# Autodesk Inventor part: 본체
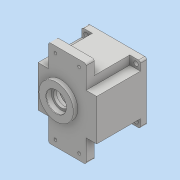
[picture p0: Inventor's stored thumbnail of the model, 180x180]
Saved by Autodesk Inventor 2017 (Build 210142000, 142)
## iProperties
Part Number: 본체
Material: 일반
Document SubType Name: Modeling
Designer: user
Density: 1 g/cm^3
Appearance: 기본값
Author: user
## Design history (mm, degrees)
sketch "스케치1"
  geometry: L1 (-30, 70)-(30, 70); L2 (30, -70)-(-30, -70); L3 (-30, 70)-(30, -70); L4 (30, 70)-(-30, -70); L5 (47, 33)-(47, -33); L6 (-47, -33)-(-47, 33); L7 (-47, 33)-(47, -33); L8 (47, 33)-(-47, -33); L9 (30, 70)-(30, 33); L10 (30, -33)-(30, -70); L11 (-47, 33)-(-30, 33); L12 (30, 33)-(47, 33); L13 (-30, -70)-(-30, -33); L14 (-30, 33)-(-30, 70); L15 (47, -33)-(30, -33); L16 (-30, -33)-(-47, -33); 1 further point
  constraints: 32 end point, 10 parallel, 4 midpoint, 4 perpendicular, 3 horizontal
  dimensions: "d6" = 60 distance of L2.start L2.end; "d7" = 140 distance of L1.end L2.start; "d8" = 94 distance of L5.end L6.start; "d9" = 66 distance of L5.start L5.end; "d10" = 60 distance of L1.start L1.end; "d11" = 66 distance of L6.start L6.end; "d12" = 37 distance of L11.end L1.start; "d13" = 37 distance of L2.end L13.end
extrude "돌출1" new body sketch "스케치1" distance "d14" = 13; taper "d15" = 0 deg
sketch "스케치2"
  geometry: L1 (-30, 33)-(-30, 70) reference; L2 (30, -33)-(47, -33) reference; L3 (47, 33)-(47, -33); L4 (-47, -33)-(-47, 33); L5 (-47, 33)-(47, -33); L6 (47, 33)-(-47, -33); L7 (30, -70)-(30, -33) reference; L8 (-30, 47)-(30, 47); L9 (30, -47)-(-30, -47); L10 (-30, 47)-(30, -47); L11 (30, 47)-(-30, -47); L12 (30, 47)-(30, 33); L13 (30, -33)-(30, -47); L14 (-47, 33)-(-30, 33); L15 (30, 33)-(47, 33); L16 (47, -33)-(30, -33); L17 (-30, -33)-(-47, -33); L18 (-30, -47)-(-30, -33); L19 (-30, 33)-(-30, 47); 1 further point
  constraints: 32 end point, 10 parallel, 4 midpoint, 4 perpendicular, 3 horizontal, 1 point on line
  dimensions: "d31" = 94 distance of L8.end L9.start; "d32" = 60 distance of L8.start L8.end; "d33" = 66 distance of L4.start L4.end; "d34" = 60 distance of L9.start L9.end; "d35" = 17 distance of L4.end L14.end
extrude "돌출2" join sketch "스케치2" distance "d16" = 57; taper "d17" = 0 deg
sketch "스케치3"
  geometry: L1 (47, -47)-(-47, -47); L2 (-47, -47)-(-47, 47); L3 (-47, 47)-(47, 47); L4 (47, 47)-(47, -47); L5 (47, -47)-(-47, 47); L6 (-47, -47)-(47, 47); 1 further point
  constraints: 12 end point, 2 midpoint, 2 parallel, 1 horizontal, 1 perpendicular
  dimensions: "d18" = 94 distance of L2.end L3.end; "d19" = 94 distance of L1.end L2.end
extrude "돌출3" join sketch "스케치3" distance "d20" = 10; taper "d21" = 0 deg
sketch "스케치4"
  geometry: C1 r 43 at (0, 0); 1 further point
  constraints: 1 centre point, 1 coincident
  dimensions: "d22" = 86 diameter of C1
extrude "돌출4" cut sketch "스케치4" distance "d23" = 9; taper "d24" = 0 deg
sketch "스케치5"
  geometry: C1 r 40 at (0, 0); 1 further point
  constraints: 1 centre point, 1 coincident
  dimensions: "d30" = 80 diameter of C1
extrude "돌출5" cut sketch "스케치5" distance "d36" = 62; taper "d37" = 0 deg
sketch "스케치6"
  geometry: L1 (3.994, -35.778)-(3.994, -39.8); L2 (3.994, -35.778)-(8.016, -35.778); L3 (-3.994, -35.778)-(-3.994, -39.8); L4 (-3.994, -35.778)-(0.029, -35.778); L5 (-3.994, 35.778)-(-3.994, 36.333); L6 (-3.994, 35.778)-(-3.439, 35.778); L7 (3.994, 35.778)-(3.994, 36.333); L8 (3.994, 35.778)-(4.549, 35.778); A1 r 36 centre (0, 0) between (0, -36) and (0, 36); A2 r 4 centre (0, -36) between (3.994, -35.778) and (-3.994, -35.778); A3 r 4 centre (0, 36) between (-3.994, 36.222) and (3.994, 36.222); A4 r 40 centre (0, 0) between (-3.994, 39.8) and (3.994, 39.8) reference; A5 r 40 centre (0, 0) between (-7.561, 39.279) and (7.561, 39.279); A6 r 3 centre (-6.994, 36.333) between (-3.994, 36.333) and (-7.561, 39.279); A7 r 3 centre (6.994, 36.333) between (7.561, 39.279) and (3.994, 36.333); 1 further point
  constraints: 24 point on circle, 16 end point, 6 centre point, 4 horizontal, 4 perpendicular, 4 point on line, 4 tangent, 2 coincident, 2 equal radius, 2 vertical alignment
  dimensions: "d38" = 72 diameter of A1; "d95" = 8 diameter of A3; "d96" = 8 diameter of A2; "d97" = 90 deg angle of L1 L2; "d98" = 90 deg angle of L3 L4; "d99" = 90 deg angle of L6 L5; "d100" = 90 deg angle of L8 L7; "d101" = 3 radius of A6 (derived)
sketch "스케치14"
  geometry: L1 (0, 0)-(-11, 0); L2 (0, 0)-(20, 0); A1 r 21 centre (-11, 0) between (7.984, 8.978) and (7.984, -8.978); A2 r 15 centre (20, 0) between (7.984, -8.978) and (7.984, 8.978)
  constraints: 4 end point, 4 point on circle, 2 centre point, 2 coincident, 2 horizontal
  dimensions: "d60" = 11 distance of L1.start L1.end; "d62" = 20 distance of L1.start L2.end; "d63" = 42 diameter of A1; "d64" = 30 diameter of A2
extrude "돌출12" join sketch "스케치14" distance "d65" = 7; taper "d66" = 0 deg
sketch "스케치15"
  geometry: C1 r 17.5 at (-11, 0); A1 r 21 centre (-11, 0) between (7.984, 8.978) and (7.984, -8.978) reference; 1 further point
  constraints: 1 centre point, 1 coincident
  dimensions: "d67" = 35 diameter of C1
extrude "돌출13" cut sketch "스케치15" distance "d68" = 10; taper "d69" = 0 deg
sketch "스케치16"
  geometry: C1 r 17.5 at (0, 0) reference; C2 r 12.5 at (0, 0); 1 further point
  constraints: 1 centre point, 1 coincident
  dimensions: "d70" = 25 diameter of C2
extrude "돌출14" cut sketch "스케치16" distance "d71" = 4.7; taper "d72" = 0 deg
sketch "스케치18"
  geometry: C1 r 27.5 at (-11, 0); 2 further points
  constraints: 1 centre point, 1 coincident
  dimensions: "d73" = 55 diameter of C1
extrude "돌출15" join sketch "스케치18" distance "d74" = 7; taper "d75" = 0 deg
sketch "스케치19"
  geometry: C1 r 27.5 at (0, 0) reference; C2 r 16 at (0, 0); 1 further point
  constraints: 1 centre point, 1 coincident
  dimensions: "d76" = 32 diameter of C2
extrude "돌출16" cut sketch "스케치19" distance "d77" = 8.3; taper "d78" = 0 deg
sketch "스케치20"
  geometry: C1 r 11 at (20, 0); A1 r 15 centre (20, 0) between (7.984, -8.978) and (7.984, 8.978) reference; 1 further point
  constraints: 1 centre point, 1 coincident
  dimensions: "d79" = 22 diameter of C1
extrude "돌출17" cut sketch "스케치20" distance "d80" = 7; taper "d81" = 0 deg
sketch "스케치21"
  geometry: C1 r 11 at (0, 0) reference; C2 r 9.5 at (0, 0); 1 further point
  constraints: 1 centre point, 1 coincident
  dimensions: "d82" = 19 diameter of C2
extrude "돌출18" cut sketch "스케치21" distance "d83" = 3; taper "d84" = 0 deg
chamfer "모따기1" distance "d86" = 1; stored, may be unused: second distance "d87" = 2, angle "d88" = 45 deg
chamfer "모따기2" distance "d89" = 0.8; stored, may be unused: second distance "d90" = 2, angle "d91" = 30 deg
chamfer "모따기3" distance "d92" = 1; stored, may be unused: second distance "d93" = 2, angle "d94" = 45 deg
extrude "돌출19" join sketch "스케치6" distance "d102" = 62; taper "d103" = 0 deg
sketch "스케치22"
  geometry: A1 r 4 centre (0, -36) between (3.994, -35.778) and (-3.994, -35.778) reference; A2 r 4 centre (0, 36) between (-3.994, 35.778) and (3.994, 35.778) reference; 3 further points
  constraints: 2 coincident
hole "구멍1" sketch "스케치22" at (0, -36), (0, 36) diameter "d104" = 3.242; stored, may be unused: countersink angle "d108" = 90 deg, drill point angle "d110" = 118 deg; dims "d105" = 7, "d106" = 4, "d107" = 2, "d109" = 9
fillet "모깎기2" dims "d111" = 3
sketch "스케치23"
  geometry: L1 (40, -40)-(-40, -40); L2 (-40, -40)-(-40, 40); L3 (-40, 40)-(40, 40); L4 (40, 40)-(40, -40); L5 (40, -40)-(-40, 40); L6 (-40, -40)-(40, 40); 1 further point
  constraints: 12 end point, 2 midpoint, 2 parallel, 1 horizontal, 1 perpendicular
  dimensions: "d112" = 80 distance of L2.end L3.end; "d113" = 80 distance of L1.end L2.end
hole "구멍2" sketch "스케치23" at (-40, 40), (-40, -40), (40, -40), (40, 40) diameter "d114" = 7; stored, may be unused: countersink angle "d118" = 90 deg, drill point angle "d120" = 118 deg; dims "d115" = 7, "d116" = 4, "d117" = 2, "d119" = 9
sketch "스케치24"
  geometry: L1 (19, -60)-(-19, -60); L2 (-19, -60)-(-19, 60); L3 (-19, 60)-(19, 60); L4 (19, 60)-(19, -60); L5 (19, -60)-(-19, 60); L6 (-19, -60)-(19, 60); 1 further point
  constraints: 12 end point, 2 midpoint, 2 parallel, 1 horizontal, 1 perpendicular
  dimensions: "d121" = 38 distance of L2.end L3.end; "d122" = 120 distance of L1.end L2.end
hole "구멍3" sketch "스케치24" at (-19, -60), (19, -60), (19, 60), (-19, 60) diameter "d123" = 10; stored, may be unused: countersink angle "d127" = 90 deg, drill point angle "d129" = 0 deg; dims "d124" = 7, "d125" = 4, "d126" = 2, "d128" = 5
sketch "스케치25"
  geometry: L1 (38, 0)-(0, 0); L2 (0, 0)-(0, -120); L3 (0, -120)-(38, -120); L4 (38, -120)-(38, 0); L5 (38, 0)-(0, -120); L6 (0, 0)-(38, -120); C1 r 5 at (0, -120) reference; 1 further point
  constraints: 12 end point, 2 midpoint, 2 parallel, 1 horizontal, 1 perpendicular
hole "구멍4" sketch "스케치25" at (0, -120), (38, -120), (38, 0), (0, 0) diameter "d130" = 4.5; stored, may be unused: countersink angle "d134" = 90 deg, drill point angle "d136" = 0 deg; dims "d131" = 7, "d132" = 4, "d133" = 2, "d135" = 5
sketch "스케치26"
  geometry: L1 (77, 80)-(-11, 80) reference; L2 (33, 80)-(33, 40); 2 further points
  constraints: 2 end point, 1 coincident, 1 midpoint, 1 vertical, 1 other
  dimensions: "d137" = 40 distance of L2.start L2.end
feature "엠보싱1" sketch "스케치26" dims "d6" = 60, "d7" = 140, "d8" = 94, "d9" = 66, "d10" = 60, "d11" = 66, "d12" = 37, "d13" = 37, "d138" = 0.5, "d139" = 0
fillet "모깎기3" dims "d140" = 3
fillet "모깎기4" dims "d141" = 3
node "솔리드1"
mirror "미러1"
other parameters: "d25" = 72
